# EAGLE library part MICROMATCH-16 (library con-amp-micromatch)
MicroMaTch 16 8-215464-6 / 1-215464-6 Drawing Number C-215464 DDEController.pdf
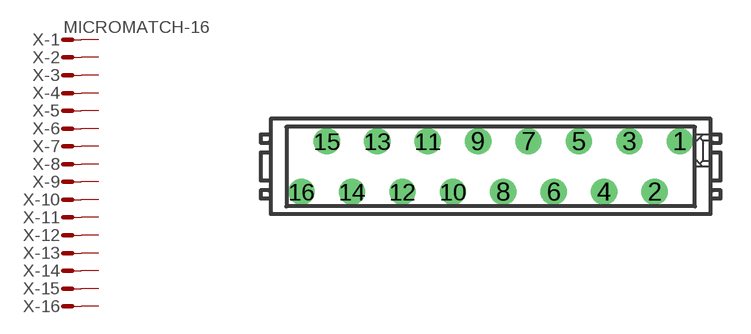
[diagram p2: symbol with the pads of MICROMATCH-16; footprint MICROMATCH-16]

Designator prefix X; gates -1=MV -2=M -3=M -4=M -5=M -6=M -7=M -8=M -9=M -10=M -11=M -12=M -13=M -14=M -15=M -16=M

## MICROMATCH-16 (MF: FARNELL; MPN: 8-215464-6; OC_FARNELL: 3784680; OC_NEWARK: 26H3309)  [MICROMATCH-16]
1  -1:S  pas
2  -2:S  pas
3  -3:S  pas
4  -4:S  pas
5  -5:S  pas
6  -6:S  pas
7  -7:S  pas
8  -8:S  pas
9  -9:S  pas
10  -10:S  pas
11  -11:S  pas
12  -12:S  pas
13  -13:S  pas
14  -14:S  pas
15  -15:S  pas
16  -16:S  pas

## Footprint MICROMATCH-16 (pad centres in mm)
MicroMaTch 16 8-215464-6 / 1-215464-6 Drawing Number C-215464 DDEController.pdf
drill 0.813 round: 1 9.525,1.27; 2 8.255,-1.27; 3 6.985,1.27; 4 5.715,-1.27; 5 4.445,1.27; 6 3.175,-1.27; 7 1.905,1.27; 8 0.635,-1.27; 9 -0.635,1.27; 10 -1.905,-1.27; 11 -3.175,1.27; 12 -4.445,-1.27; 13 -5.715,1.27; 14 -6.985,-1.27; 15 -8.255,1.27; 16 -9.525,-1.27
